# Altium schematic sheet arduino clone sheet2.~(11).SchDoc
size A; SheetNumber: 2; SheetTotal: 2
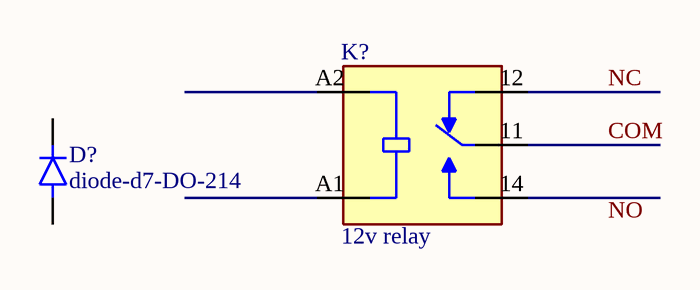
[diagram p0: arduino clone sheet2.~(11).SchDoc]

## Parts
D?  diode-d7-DO-214  [diode-d7-DO-214]
K?  12v relay  [RELAY_833H-1C-S-12VDC]

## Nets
COM: K?.11(COM)
NC: K?.12(NC)

Not connected (* = marked no-connect by the designer): D? A C; K? 14(NO) A1(COIL2) A2(COIL1)

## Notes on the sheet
- Labels drawn without touching a wire or pin: NO

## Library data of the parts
D? = diode-d7-DO-214: MF: Diodes Inc.; MP: S1M-13-F
K? = 833H-1C-S-12VDC: 833H Series 10 A SPDT 12 VDC Through Hole Miniature Sugar Cube Power Relay; MF: Song Chuan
